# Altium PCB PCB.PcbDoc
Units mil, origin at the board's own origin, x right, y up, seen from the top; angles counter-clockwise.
Board outline 1989.29 x 3148.1 mil, 2 copper layers (Signal1, Signal4); 8 components, 0 nets, 106 pads, 0 vias.
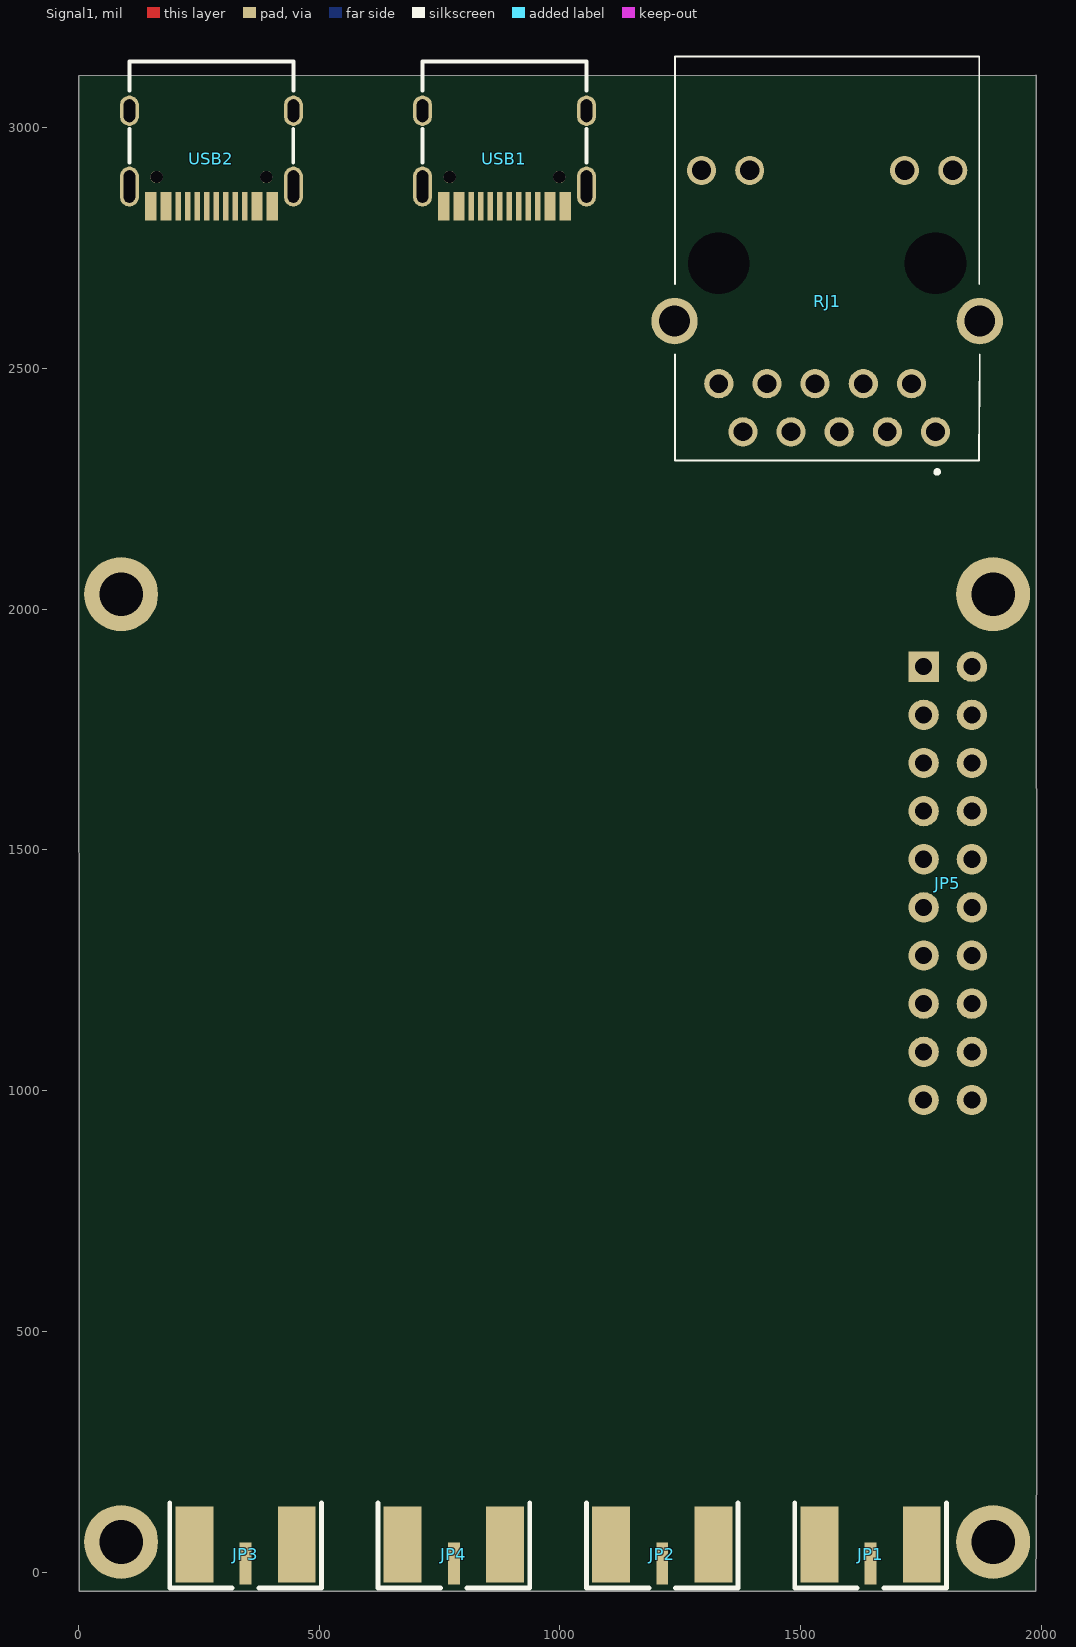
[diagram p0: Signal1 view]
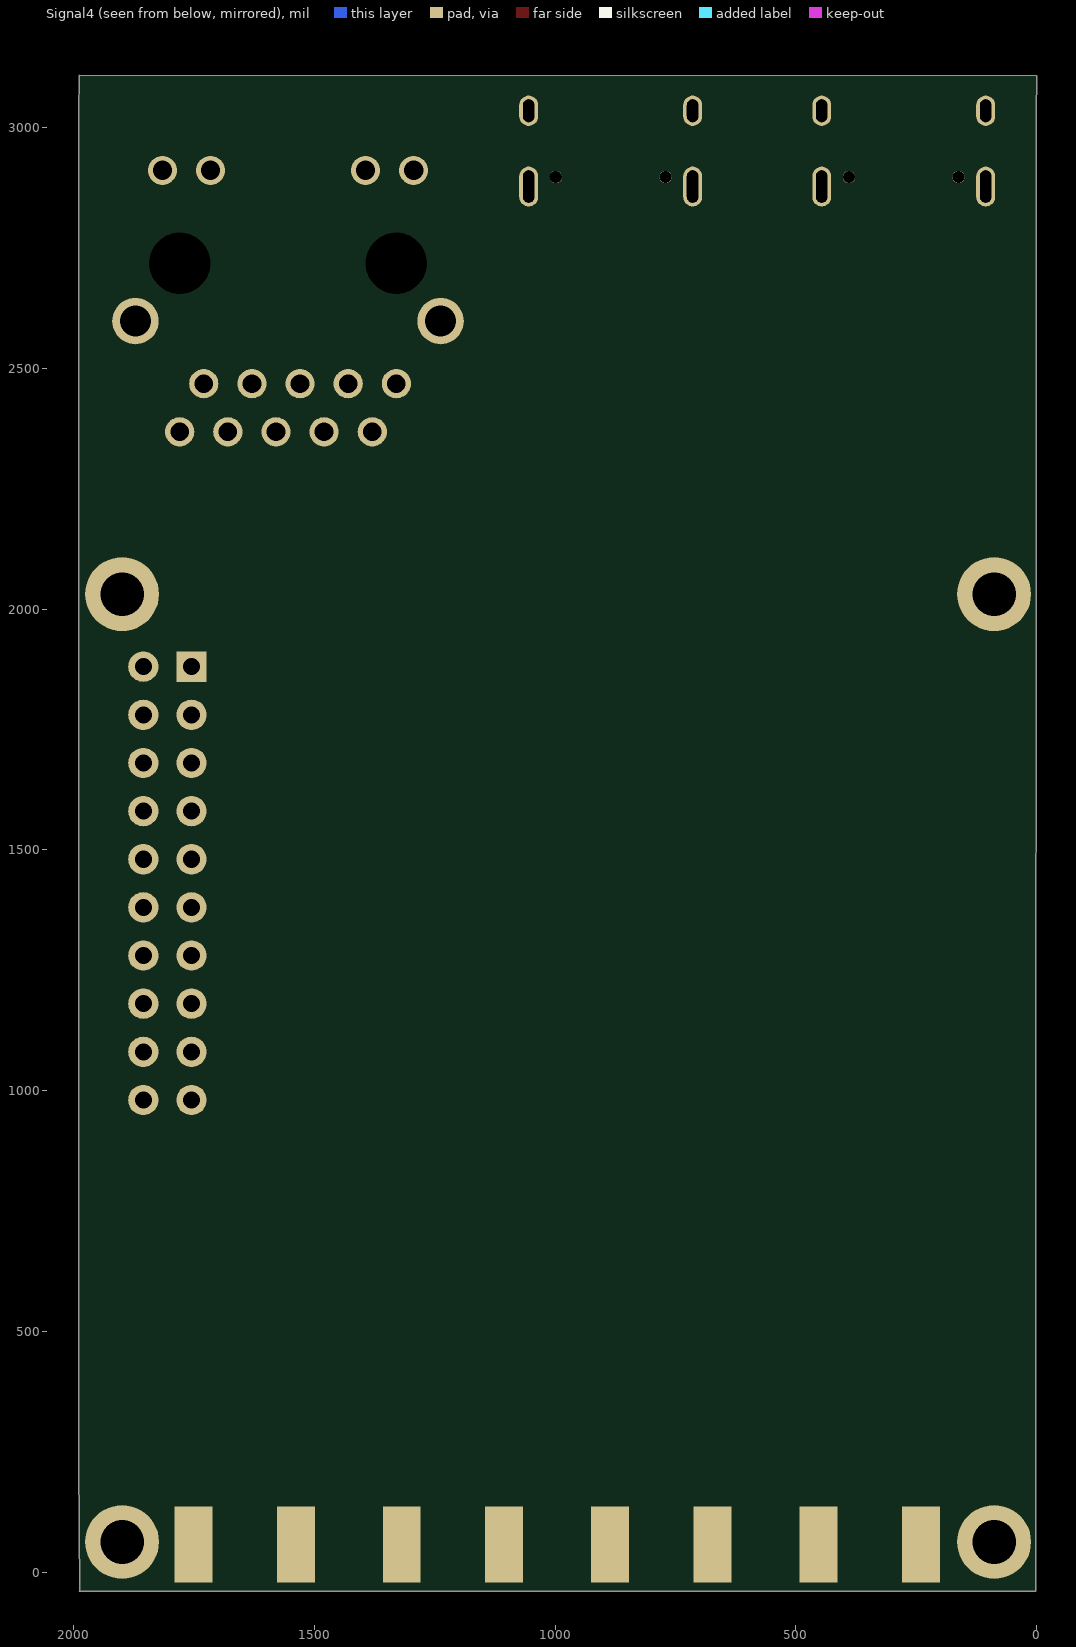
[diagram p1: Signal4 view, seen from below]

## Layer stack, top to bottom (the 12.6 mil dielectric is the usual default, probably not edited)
Top Solder: solder mask 0.4, Solder Resist, Dk 3.5
Signal1: signal copper 1.4
Dielectric 1: dielectric 12.6, FR-4, Dk 4.8
Signal4: signal copper 1.4
Bottom Solder: solder mask 0.4, Solder Resist, Dk 3.5

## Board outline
1.53,-40 1.1,3027.61 0.41,3108 1988.6,3108.1 1988.61,3108.09 1989.3,3027.7 1989.7,226.8 1987.92,-39.9 1988.19,-39.9

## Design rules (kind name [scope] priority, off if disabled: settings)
Clearance [All] p1: gap=4 ignorepadtopadclearanceinfootprint=TRUE
ComponentClearance [All] p1: gap=-100 collisioncheckmode=3 verticalgap=10 showdistances=FALSE
DiffPairsRouting DiffPair_RFDiffPairsRoutingRF [InDifferentialPairClass('RF_100_rx')] p1: maxlimit=10 minlimit=4 mostfreqgap=10 toplayer_prefgap=5 toplayer_minwidth=4 toplayer_maxwidth=15 toplayer_prefwidth=4.17 bottomlayer_mingap=10 bottomlayer_minwidth=15 bottomlayer_maxwidth=15 bottomlayer_prefwidth=15 maxuncoupledlength=500
DiffPairsRouting [All] p2: maxlimit=10 minlimit=5 mostfreqgap=5 toplayer_minwidth=4 toplayer_maxwidth=100 toplayer_prefwidth=4.07 bottomlayer_minwidth=4 bottomlayer_maxwidth=100 bottomlayer_prefwidth=4.07 maxuncoupledlength=500
FanoutControl Fanout_BGA [IsBGA] p1: bgadir=Out bgaviamode=Closest fanoutstyle=UnderPads fanoutdirection=Alternating viagrid=1 // Fanout_BGA (Default Rule)
FanoutControl Fanout_LCC [IsLCC] p2: bgadir=Out bgaviamode=Centered fanoutstyle=UnderPads fanoutdirection=Alternating viagrid=1 // Fanout_LCC (Default Rule)
FanoutControl Fanout_SOIC [IsSOIC] p3: bgadir=Out bgaviamode=Centered fanoutstyle=UnderPads fanoutdirection=Alternating viagrid=1 // Fanout_SOIC (Default Rule)
FanoutControl Fanout_Small [(CompPinCount < 5)] p4: bgadir=Out bgaviamode=Centered fanoutstyle=UnderPads fanoutdirection=OutThenIn viagrid=1 // Fanout_Small (Default Rule)
FanoutControl Fanout_Default [All] p5: bgadir=Out bgaviamode=Centered fanoutstyle=UnderPads fanoutdirection=Alternating viagrid=1 // Fanout_Default (Default Rule)
HoleSize [All] p1: absolutevalues=TRUE maxlimit=200 minlimit=1 maxpercent=80.000 minpercent=20.000
HoleToHoleClearance [All] p1: gap=8 allowstackedmicrovias=TRUE
MatchedLengths DiffPair_RFMatchedLengthsRF [InDifferentialPairClass('RF_100_rx')] p1: tolerance=100 checknetsindiffpair=FALSE checkdiffpairvsdiffpair=TRUE checkxsignals=TRUE checkothers=TRUE
MinimumSolderMaskSliver [All] p1: minsoldermaskwidth=0
PolygonConnect [All] p1: connectstyle=Direct reliefconductorwidth=10 reliefentries=4 polygonreliefangle="90 Angle" airgapwidth=10
RoutingVias [All] p1: holewidth=11.81 width=18 viastyle="Through Hole" minholewidth=11.81 minwidth=15.75 maxholewidth=200 maxwidth=200
SilkToSilkClearance [All] p1: silktosilkclearance=0
SilkToSolderMaskClearance [IsPad] p1: minsilkscreentomaskgap=0 clearancetoexposedcopper=TRUE
SolderMaskExpansion [All] p1: expansion=4 istentingtop=FALSE
UnRoutedNet [All] p1: checkbadconnections=TRUE
Width [All] p1: maxlimit=100 minlimit=4 preferedwidth=4 minimp=50.000000 maximp=50.000000 favimp=50.000000
17 further rules are at their usual default settings.

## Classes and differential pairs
differential pair TX2A: +TX2A_P -TX2A_N
differential pair TX1A: +TX1A_P -TX1A_N
differential pair 1V8_IO7: +1V8_IO7_P -1V8_IO7_N
differential pair 1V8_IO5: +1V8_IO5_P -1V8_IO5_N
differential pair 1V8_IO3: +1V8_IO3_P -1V8_IO3_N
differential pair 1V8_IO1: +1V8_IO1_P -1V8_IO1_N
differential pair PHY_MDI3: +PHY_MDI3_P -PHY_MDI3_N
differential pair PHY_MDI2: +PHY_MDI2_P -PHY_MDI2_N
differential pair PHY_MDI1: +PHY_MDI1_P -PHY_MDI1_N
differential pair PHY_MDI0: +PHY_MDI0_P -PHY_MDI0_N
differential pair TX_FRAME: +TX_FRAME_P -TX_FRAME_N
differential pair TX_D5: +TX_D5_P -TX_D5_N
differential pair TX_D4: +TX_D4_P -TX_D4_N
differential pair TX_D3: +TX_D3_P -TX_D3_N
differential pair TX_D2: +TX_D2_P -TX_D2_N
differential pair TX_D1: +TX_D1_P -TX_D1_N
differential pair TX_D0: +TX_D0_P -TX_D0_N
differential pair RX_FRAME: +RX_FRAME_P -RX_FRAME_N
differential pair RX_D5: +RX_D5_P -RX_D5_N
differential pair RX_D4: +RX_D4_P -RX_D4_N
differential pair RX_D3: +RX_D3_P -RX_D3_N
differential pair RX_D2: +RX_D2_P -RX_D2_N
differential pair RX_D1: +RX_D1_P -RX_D1_N
differential pair RX_D0: +RX_D0_P -RX_D0_N
differential pair RX2A: +RX2A_P -RX2A_N
differential pair RX1A: +RX1A_P -RX1A_N
differential pair OTG: +OTG_P -OTG_N
differential pair JTAG_USB: +JTAG_USB_P -JTAG_USB_N
differential pair FB_CLK: +FB_CLK_P -FB_CLK_N
differential pair DATA_CLK: +DATA_CLK_P -DATA_CLK_N
differential pair DDR3_DQS3: +DDR3_DQS3_P -DDR3_DQS3_N
differential pair DDR3_DQS2: +DDR3_DQS2_P -DDR3_DQS2_N
differential pair DDR3_DQS1: +DDR3_DQS1_P -DDR3_DQS1_N
differential pair DDR3_DQS0: +DDR3_DQS0_P -DDR3_DQS0_N
differential pair DDR3_CLK: +DDR3_CLK_P -DDR3_CLK_N

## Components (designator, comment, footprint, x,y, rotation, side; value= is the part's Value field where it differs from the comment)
JP1 "SMA" "SMA-KE - 0.5MM" 1645,57.2 r180 top
JP2 "SMA" "SMA-KE - 0.5MM" 1212.34,57.2 r180 top
JP3 "SMA" "SMA-KE - 0.5MM" 347.01,57.2 r180 top
JP4 "SMA" "SMA-KE - 0.5MM" 779.67,57.2 r180 top
JP5 "Header 2X10" HDR2.54-LI-2X10P 1805.4,1430.4 r270 top
RJ1 "HR911130A" HR911130A 1554.9,2714.3 r0 top
USB1 "Type-C" TYPE-C-16P 884.8,2935.68 r90 top
USB2 "Type-C" TYPE-C-16P 276.2,2935.68 r90 top

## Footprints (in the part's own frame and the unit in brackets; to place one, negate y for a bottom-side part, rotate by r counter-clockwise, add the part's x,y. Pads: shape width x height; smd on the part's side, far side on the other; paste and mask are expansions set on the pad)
HDR2.54-LI-2X10P [mm]
  rect 1.6x1.6 hole 0.9: 1(-11.43,-1.27)
  round 1.6 hole 0.9: 2(-11.43,1.27) 3(-8.89,-1.27) 4(-8.89,1.27) 5(-6.35,-1.27) 6(-6.35,1.27) 7(-3.81,-1.27) 8(-3.81,1.27) 9(-1.27,-1.27) 10(-1.27,1.27) 11(1.27,-1.27) 12(1.27,1.27) 13(3.81,-1.27) 14(3.81,1.27) 15(6.35,-1.27) 16(6.35,1.27) 17(8.89,-1.27) 18(8.89,1.27) 19(11.43,-1.27) 20(11.43,1.27)
  body extent -12.7,-2.54 12.7,2.54, height 8.5
HR911130A [mm]
  round 1.54 hole 0.99: 1(5.715,-8.794) 2(4.445,-6.254) 3(3.175,-8.794) 4(1.905,-6.254) 5(0.635,-8.794) 6(-0.635,-6.254) 7(-1.905,-8.794) 8(-3.175,-6.254) 9(-4.445,-8.794) 10(-5.715,-6.254)
  round 1.53 hole 1.02: 11(-6.625,4.996) 12(-4.085,4.996) 13(4.085,4.996) 14(6.625,4.996)
  round 2.445 hole 1.63: 15(-8.05,-2.954) 16(8.05,-2.954)
  round 1.625 hole 3.25 unplated: 17(-5.715,0.096) 18(5.715,0.096)
  silkscreen extent -8.02,-11 8.05,11, body extent -7.94,-10.4 7.94,11, height 13.45
"SMA-KE - 0.5MM" [mm] "SMA 偏脚射频天线座"
  rect 0.62x2.2 smd: 1(0,1)
  rect 2x4 smd: 2(-2.7,0) 2(2.7,0)
  rect 2x4 smd far side: 2(-2.7,0) 2(2.7,0)
  silkscreen extent -4,-2.2 4,2.3, body extent -3.25,-1.3 3.25,12.2, height 3.75
TYPE-C-16P [mm]
  round 0.65 hole 0.65: 0(-0.98,2.89) 0(-0.98,-2.89)
  oval 1.6x1 hole 0.6 slot 1.2 at 0 deg: 1(2.52,4.325) 2(2.52,-4.325)
  oval 2.1x1 hole 0.6 slot 1.7 at 0 deg: 3(-1.48,-4.325) 4(-1.48,4.325)
  rect 1.5x0.3 smd: A1(-2.52,-3.35) A4(-2.52,-2.55) A5(-2.52,-1.25) A6(-2.52,-0.25) A7(-2.52,0.25) A8(-2.52,1.25) A9(-2.52,2.55) A12(-2.52,3.35) B1(-2.52,3.05) B4(-2.52,2.25) B5(-2.52,1.75) B6(-2.52,0.75) B7(-2.52,-0.75) B8(-2.52,-1.75) B9(-2.52,-2.25) B12(-2.52,-3.05)
  silkscreen extent -0.22,-4.33 5.12,4.33, body extent -2.54,-4.46 5.21,4.49, height 3.36

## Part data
JP1 JP2 JP3 JP4: "SMA-2.4G射频天线接口"
JP5: library part "Header 10X2", "10*2P接插件"
RJ1: library part HR911130A_1, JLCPCB Part Class="Extended Part", Manufacturer=HANRUN(汉仁)
USB1: library part Type-C-16P, "带通信"

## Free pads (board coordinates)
  round 153.54 hole 90.55: 14(88.54,62.5) 14(88.54,2031) 14(1899.56,62.5) 14(1899.56,2031)

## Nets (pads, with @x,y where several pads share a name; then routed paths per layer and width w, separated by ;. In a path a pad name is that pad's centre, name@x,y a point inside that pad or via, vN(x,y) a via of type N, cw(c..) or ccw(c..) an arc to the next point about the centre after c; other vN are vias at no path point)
pads on no net: JP1.1 JP1.2 JP2.1 JP2.2 JP3.1 JP3.2 JP4.1 JP4.2 JP5.1 JP5.2 JP5.3 JP5.4 JP5.5 JP5.6 JP5.7 JP5.8 JP5.9 JP5.10 JP5.11 JP5.12 JP5.13 JP5.14 JP5.15 JP5.16 JP5.17 JP5.18 JP5.19 JP5.20 RJ1.1 RJ1.2 RJ1.3 RJ1.4 RJ1.5 RJ1.6 RJ1.7 RJ1.8 RJ1.9 RJ1.10 RJ1.11 RJ1.12 RJ1.13 RJ1.14 RJ1.15 RJ1.16 RJ1.17 RJ1.18 USB1.0 USB1.1 USB1.2 USB1.3 USB1.4 USB1.A1 USB1.A4 USB1.A5 USB1.A6 USB1.A7 USB1.A8 USB1.A9 USB1.A12 USB1.B1 USB1.B4 USB1.B5 USB1.B6 USB1.B7 USB1.B8 USB1.B9 USB1.B12 USB2.0 USB2.1 USB2.2 USB2.3 USB2.4 USB2.A1 USB2.A4 USB2.A5 USB2.A6 USB2.A7 USB2.A8 USB2.A9 USB2.A12 USB2.B1 USB2.B4 USB2.B5 USB2.B6 USB2.B7 USB2.B8 USB2.B9 USB2.B12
